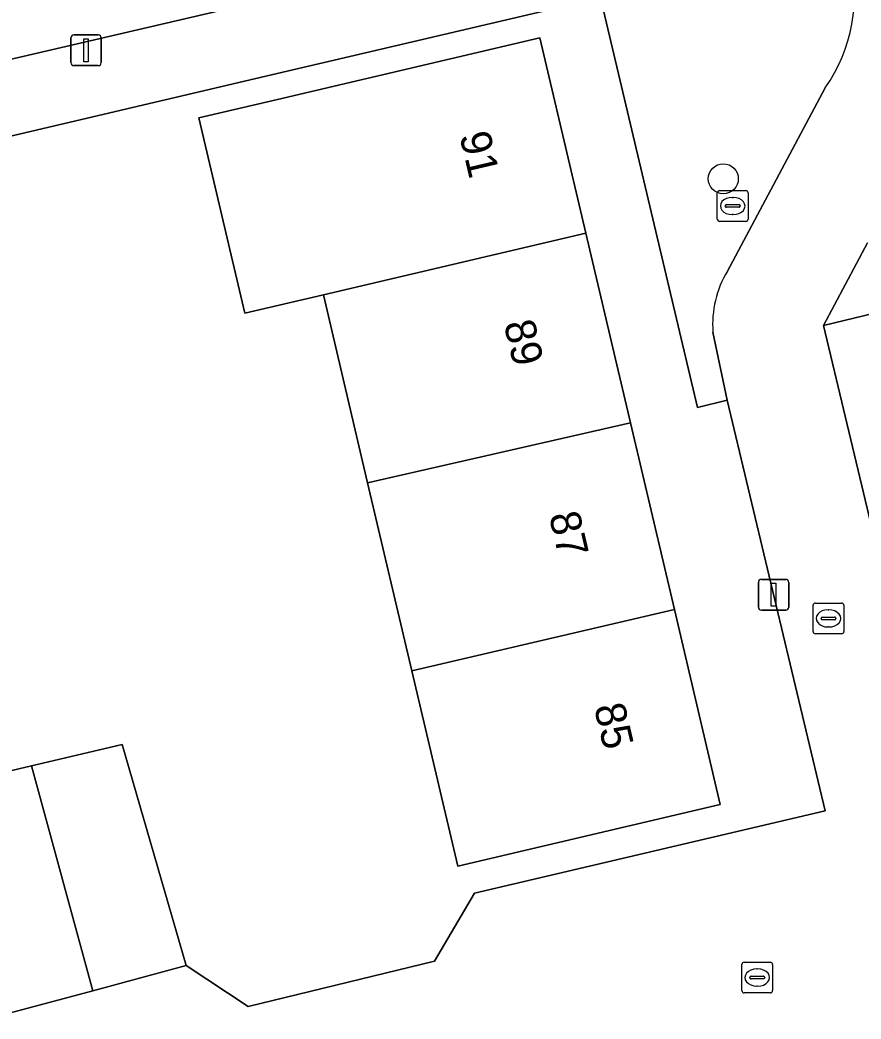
# Model space of a CAD drawing. Extents: x 157793 to 159380, y 380877 to 382313.
# Drawn here: x 158656.16 to 158683.52, y 381200.11 to 381232.61 of the extents above; entities that cross this region are included whole.
import ezdxf

# ---------------------------------------------------------------- set-up
doc = ezdxf.new("R2010")
doc.units = 0
for name, color, linetype in [('IMGEO_Boom', 7, 'Continuous'), ('IMGEO_Erf', 7, 'Continuous'), ('IMGEO_Kolk', 7, 'Continuous'), ('IMGEO_Lichtmast', 7, 'Continuous'), ('IMGEO_Muur', 7, 'Continuous'), ('IMGEO_Pand', 7, 'Continuous'), ('IMGEO_Pand_nummerreeks', 7, 'Continuous'), ('IMGEO_Rijbaan_lokaal_open', 7, 'Continuous'), ('IMGEO_Rioolput', 7, 'Continuous'), ('IMGEO_Voetpad_open', 7, 'Continuous')]:
    doc.layers.add(name, color=color, linetype=linetype)

msp = doc.modelspace()

# ---------------------------------------------------------------- linework, layer by layer
at = {"layer": 'IMGEO_Boom'}
msp.add_circle((158679.041, 381227.443), 0.489, dxfattribs=at)
at = {"layer": 'IMGEO_Erf'}
msp.add_lwpolyline([(158640.774, 381261.468), (158641.816, 381257.081), (158642.116, 381255.85), (158642.419, 381254.605), (158642.761, 381253.199), (158645.242, 381253.788), (158646.142, 381250), (158646.255, 381249.524), (158647.255, 381245.311), (158644.774, 381244.722), (158648.376, 381229.59), (158649.835, 381229.931), (158648.124, 381237.133), (158647.118, 381241.367), (158649.63, 381241.963), (158650.631, 381237.747), (158650.655, 381237.648), (158653.009, 381238.207), (158654.705, 381231.068), (158666.978, 381233.931), (158674.495, 381235.697), (158681.372, 381237.445), (158675.438, 381262.839)], dxfattribs=at)
for points in [[(158679.171, 381220.243), (158678.197, 381220.001), (158675.05, 381233.346), (158664.347, 381230.829), (158650.313, 381227.528), (158648.943, 381227.206), (158651.993, 381214.392), (158653.597, 381207.654), (158656.539, 381208.346), (158659.484, 381209.039), (158661.572, 381201.847), (158663.581, 381200.52), (158669.651, 381201.987), (158670.949, 381204.202), (158682.352, 381206.878)], [(158668.909, 381211.437), (158667.47, 381217.555), (158666.031, 381223.673), (158663.474, 381223.073), (158661.98, 381229.422), (158664.537, 381230.023), (158673.077, 381232.032), (158674.572, 381225.676), (158676.023, 381219.507), (158677.452, 381213.434), (158678.944, 381207.092), (158670.404, 381205.083)], [(158714.924, 381217.35), (158711.569, 381216.561), (158711.214, 381218.07), (158705.222, 381216.66), (158699.092, 381215.218), (158692.927, 381213.768), (158686.609, 381212.282), (158684.622, 381220.73), (158690.971, 381222.224), (158697.166, 381223.681), (158703.235, 381225.109), (158709.603, 381226.607), (158710.275, 381223.751), (158713.254, 381224.452), (158711.951, 381229.839), (158682.304, 381222.668), (158684.255, 381214.5), (158686.707, 381204.195), (158687.735, 381204.417), (158694.879, 381206.182), (158695.593, 381203.15), (158696.306, 381200.119), (158717.835, 381205.337)]]:
    msp.add_lwpolyline(points, close=True, dxfattribs=at)
at = {"layer": 'IMGEO_Kolk'}
for p, q in [((158681.962, 381212.716), (158681.962, 381213.568)), ((158682.037, 381213.642), (158682.889, 381213.642)), ((158682.963, 381213.568), (158682.963, 381212.716)), ((158682.45, 381213.422), (158682.475, 381213.422)), ((158682.221, 381213.136), (158682.221, 381213.148)), ((158682.659, 381213.099), (158682.261, 381213.099)), ((158682.264, 381213.185), (158682.662, 381213.185)), ((158682.705, 381213.148), (158682.705, 381213.136)), ((158682.889, 381212.642), (158682.037, 381212.642)), ((158682.473, 381212.862), (158682.448, 381212.862)), ((158679.645, 381201.032), (158679.645, 381201.884)), ((158679.72, 381201.958), (158680.572, 381201.958)), ((158680.646, 381201.884), (158680.646, 381201.032)), ((158680.133, 381201.738), (158680.158, 381201.738)), ((158679.904, 381201.452), (158679.904, 381201.464)), ((158680.342, 381201.415), (158679.944, 381201.415)), ((158679.947, 381201.501), (158680.345, 381201.501)), ((158680.388, 381201.464), (158680.388, 381201.452)), ((158680.572, 381200.958), (158679.72, 381200.958)), ((158680.156, 381201.178), (158680.131, 381201.178))]:
    msp.add_line(p, q, dxfattribs=at)
for points in [[(158681.962, 381212.716), (158681.962, 381213.568)], [(158682.037, 381213.642), (158682.889, 381213.642)], [(158682.963, 381213.568), (158682.963, 381212.716)], [(158682.889, 381212.642), (158682.037, 381212.642)], [(158679.645, 381201.032), (158679.645, 381201.884)], [(158679.72, 381201.958), (158680.572, 381201.958)], [(158680.646, 381201.884), (158680.646, 381201.032)], [(158680.572, 381200.958), (158679.72, 381200.958)]]:
    msp.add_lwpolyline(points, dxfattribs=at)
for centre, radius, start, end in [((158682.039, 381213.566), 0.0765, 91.552, 178.448), ((158682.039, 381213.566), 0.0765, 91.552, 178.448), ((158682.887, 381213.566), 0.0765, 1.552, 88.448), ((158682.887, 381213.566), 0.0765, 1.552, 88.448), ((158682.261, 381213.145), 0.0403, 85.8775, 175.7526), ((158682.258, 381213.135), 0.0366, 178.938, 274.7102), ((158682.662, 381213.142), 0.043, 264.8664, 352.4533), ((158682.666, 381213.147), 0.0386, 1.7309, 96.639), ((158682.039, 381212.718), 0.0765, 181.552, 268.448), ((158682.039, 381212.718), 0.0765, 181.552, 268.448), ((158682.887, 381212.718), 0.0765, 271.552, 358.448), ((158682.887, 381212.718), 0.0765, 271.552, 358.448), ((158679.722, 381201.882), 0.0765, 91.552, 178.448), ((158679.722, 381201.882), 0.0765, 91.552, 178.448), ((158680.57, 381201.882), 0.0765, 1.552, 88.448), ((158680.57, 381201.882), 0.0765, 1.552, 88.448), ((158679.944, 381201.461), 0.0403, 85.8775, 175.7526), ((158679.941, 381201.451), 0.0366, 178.938, 274.7102), ((158680.345, 381201.458), 0.043, 264.8664, 352.4533), ((158680.349, 381201.463), 0.0386, 1.7309, 96.639), ((158679.722, 381201.034), 0.0765, 181.552, 268.448), ((158679.722, 381201.034), 0.0765, 181.552, 268.448), ((158680.57, 381201.034), 0.0765, 271.552, 358.448), ((158680.57, 381201.034), 0.0765, 271.552, 358.448)]:
    msp.add_arc(centre, radius, start, end, dxfattribs=at)
for centre, major_axis, ratio, start_param, end_param in [((158682.449, 381213.142), (-0.387, 0.002), 0.722429, 4.712389, 7.853982), ((158682.474, 381213.142), (-0.39, 0.002), 0.717154, 1.570796, 4.712389), ((158680.132, 381201.458), (-0.387, 0.002), 0.722429, 4.712389, 7.853982), ((158680.157, 381201.458), (-0.39, 0.002), 0.717154, 1.570796, 4.712389)]:
    msp.add_ellipse(centre, major_axis=major_axis, ratio=ratio, start_param=start_param, end_param=end_param, dxfattribs=at)
at = {"layer": 'IMGEO_Lichtmast'}
for p, q in [((158657.915, 381232.125), (158658.705, 381232.125)), ((158658.705, 381232.125), (158657.915, 381232.125)), ((158657.815, 381231.225), (158657.815, 381232.025)), ((158657.815, 381232.025), (158657.815, 381231.225)), ((158658.805, 381232.025), (158658.805, 381231.225)), ((158658.805, 381231.225), (158658.805, 381232.025)), ((158658.705, 381231.125), (158657.915, 381231.125)), ((158657.915, 381231.125), (158658.705, 381231.125)), ((158680.182, 381213.51), (158680.182, 381214.31)), ((158680.182, 381214.31), (158680.182, 381213.51)), ((158680.282, 381214.41), (158681.072, 381214.41)), ((158681.072, 381214.41), (158680.282, 381214.41)), ((158681.172, 381214.31), (158681.172, 381213.51)), ((158681.172, 381213.51), (158681.172, 381214.31)), ((158681.072, 381213.41), (158680.282, 381213.41)), ((158680.282, 381213.41), (158681.072, 381213.41))]:
    msp.add_line(p, q, dxfattribs=at)
for points in [[(158658.235, 381232), (158658.385, 381232), (158658.385, 381231.25), (158658.235, 381231.25), (158658.235, 381232)], [(158680.602, 381214.285), (158680.752, 381214.285), (158680.752, 381213.535), (158680.602, 381213.535), (158680.602, 381214.285)]]:
    msp.add_lwpolyline(points, dxfattribs=at)
for centre, start, end in [((158657.915, 381232.025), 90, 180), ((158657.915, 381232.025), 90, 180), ((158658.705, 381232.025), 0, 90), ((158658.705, 381232.025), 360, 90), ((158657.915, 381231.225), 180, 270), ((158657.915, 381231.225), 180, 270), ((158658.705, 381231.225), 270, 0), ((158658.705, 381231.225), 270, 0), ((158680.282, 381214.31), 90, 180), ((158680.282, 381214.31), 90, 180), ((158681.072, 381214.31), 0, 90), ((158681.072, 381214.31), 360, 90), ((158680.282, 381213.51), 180, 270), ((158680.282, 381213.51), 180, 270), ((158681.072, 381213.51), 270, 0), ((158681.072, 381213.51), 270, 0)]:
    msp.add_arc(centre, 0.1, start, end, dxfattribs=at)
at = {"layer": 'IMGEO_Muur'}
for points in [[(158666.978, 381233.931), (158654.705, 381231.068)], [(158650.313, 381227.528), (158664.347, 381230.829)]]:
    msp.add_lwpolyline(points, dxfattribs=at)
at = {"layer": 'IMGEO_Pand'}
for points in [[(158673.077, 381232.032), (158664.537, 381230.023), (158661.98, 381229.422), (158663.474, 381223.073), (158666.031, 381223.673), (158674.572, 381225.676)], [(158676.023, 381219.507), (158674.572, 381225.676), (158666.031, 381223.673), (158667.47, 381217.555)], [(158676.023, 381219.507), (158667.47, 381217.555), (158668.909, 381211.437), (158677.452, 381213.434)], [(158668.909, 381211.437), (158670.404, 381205.083), (158678.944, 381207.092), (158677.452, 381213.434)], [(158656.539, 381208.346), (158658.534, 381201.029), (158661.572, 381201.847), (158659.484, 381209.039)], [(158656.539, 381208.346), (158653.597, 381207.654), (158655.652, 381200.253), (158658.534, 381201.029)]]:
    msp.add_lwpolyline(points, close=True, dxfattribs=at)
at = {"layer": 'IMGEO_Rijbaan_lokaal_open'}
for points in [[(158682.358, 381230.4), (158679.177, 381224.443)], [(158689.154, 381198.437), (158688.441, 381201.468), (158687.735, 381204.417), (158686.707, 381204.195), (158684.255, 381214.5), (158682.304, 381222.668), (158683.727, 381225.361)], [(158678.706, 381222.455), (158679.171, 381220.243), (158682.352, 381206.878), (158670.949, 381204.202), (158669.651, 381201.987), (158663.581, 381200.52), (158661.572, 381201.847), (158658.534, 381201.029), (158655.652, 381200.253), (158656.869, 381195.254)]]:
    msp.add_lwpolyline(points, dxfattribs=at)
for centre, radius, start, end in [((158677.917, 381233.469), 5.399, 325.3533, 13.417), ((158682.013, 381222.721), 3.318, 148.7409, 184.6014)]:
    msp.add_arc(centre, radius, start, end, dxfattribs=at)
at = {"layer": 'IMGEO_Rioolput'}
for p, q in [((158678.846, 381226.133), (158678.846, 381226.985)), ((158678.921, 381227.059), (158679.773, 381227.059)), ((158679.847, 381226.985), (158679.847, 381226.133)), ((158679.105, 381226.553), (158679.105, 381226.565)), ((158679.148, 381226.602), (158679.546, 381226.602)), ((158679.334, 381226.839), (158679.359, 381226.839)), ((158679.589, 381226.565), (158679.589, 381226.553)), ((158679.543, 381226.516), (158679.145, 381226.516)), ((158679.357, 381226.279), (158679.332, 381226.279)), ((158679.773, 381226.059), (158678.921, 381226.059))]:
    msp.add_line(p, q, dxfattribs=at)
for points in [[(158678.846, 381226.133), (158678.846, 381226.985)], [(158678.921, 381227.059), (158679.773, 381227.059)], [(158679.847, 381226.985), (158679.847, 381226.133)], [(158679.773, 381226.059), (158678.921, 381226.059)]]:
    msp.add_lwpolyline(points, dxfattribs=at)
for centre, radius, start, end in [((158678.923, 381226.983), 0.0765, 91.552, 178.448), ((158678.923, 381226.983), 0.0765, 91.552, 178.448), ((158679.771, 381226.983), 0.0765, 1.552, 88.448), ((158679.771, 381226.983), 0.0765, 1.552, 88.448), ((158679.145, 381226.562), 0.0403, 85.8775, 175.7526), ((158679.55, 381226.564), 0.0386, 1.7309, 96.639), ((158679.142, 381226.552), 0.0366, 178.938, 274.7102), ((158679.546, 381226.559), 0.043, 264.8664, 352.4533), ((158678.923, 381226.135), 0.0765, 181.552, 268.448), ((158678.923, 381226.135), 0.0765, 181.552, 268.448), ((158679.771, 381226.135), 0.0765, 271.552, 358.448), ((158679.771, 381226.135), 0.0765, 271.552, 358.448)]:
    msp.add_arc(centre, radius, start, end, dxfattribs=at)
for centre, major_axis, ratio, start_param, end_param in [((158679.333, 381226.559), (-0.387, 0.002), 0.722429, 4.712389, 7.853982), ((158679.358, 381226.559), (-0.39, 0.002), 0.717154, 1.570796, 4.712389)]:
    msp.add_ellipse(centre, major_axis=major_axis, ratio=ratio, start_param=start_param, end_param=end_param, dxfattribs=at)
at = {"layer": 'IMGEO_Voetpad_open'}
for points in [[(158671.453, 381288.156), (158668.346, 381287.373), (158674.305, 381262.524), (158675.438, 381262.839), (158681.372, 381237.445), (158674.495, 381235.697), (158666.978, 381233.931), (158654.705, 381231.068), (158649.835, 381229.931), (158648.376, 381229.59), (158648.943, 381227.206), (158650.313, 381227.528), (158664.347, 381230.829), (158675.05, 381233.346), (158678.197, 381220.001), (158679.171, 381220.243), (158678.706, 381222.455)], [(158683.727, 381225.361), (158682.304, 381222.668), (158711.951, 381229.839), (158712.422, 381229.953), (158712.509, 381229.567), (158713.697, 381229.849), (158717.707, 381230.799), (158722.54, 381231.945)], [(158679.177, 381224.443), (158682.358, 381230.4)]]:
    msp.add_lwpolyline(points, dxfattribs=at)
for centre, radius, start, end in [((158677.917, 381233.469), 5.399, 325.3533, 13.417), ((158682.013, 381222.721), 3.318, 148.7409, 184.6014)]:
    msp.add_arc(centre, radius, start, end, dxfattribs=at)

# ---------------------------------------------------------------- texts
at = {"layer": 'IMGEO_Pand_nummerreeks'}
for s, rotation, p in [('91', 283.2351, (158670.453, 381228.858)), ('89', 283.2378, (158671.895, 381222.733)), ('87', 283.2378, (158673.362, 381216.498)), ('85', 283.2378, (158674.829, 381210.263))]:
    msp.add_text(s, height=1, rotation=rotation, dxfattribs=at).set_placement(p)

doc.saveas('drawing.dxf')
